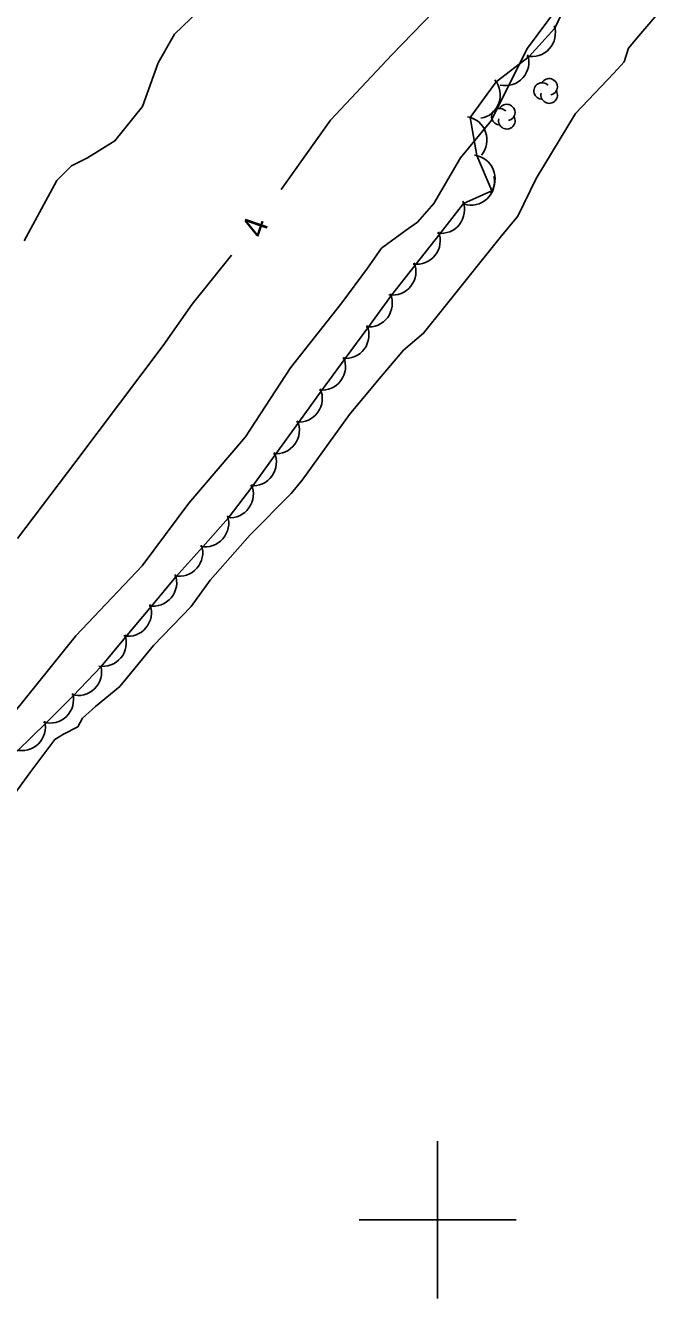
# Model space of a CAD drawing. Extents: x 643342 to 646936, y 5873857 to 5876103.
# Drawn here: x 643747.6 to 643828.6, y 5874190 to 5874351.9 of the extents above; entities that cross this region are included whole.
import ezdxf

# ---------------------------------------------------------------- set-up
doc = ezdxf.new("R2010")
doc.units = 0
for name, color, linetype in [('Niveau 2', 7, 'Continuous'), ('Niveau 4', 7, 'Continuous'), ('Niveau 44', 7, 'Continuous'), ('Niveau 61', 7, 'Continuous')]:
    doc.layers.add(name, color=color, linetype=linetype)

msp = doc.modelspace()

# ---------------------------------------------------------------- linework, layer by layer
at = {"layer": 'Niveau 2'}
for points in [[(643804.54, 5874390.56), (643804.07, 5874388.55), (643802.31, 5874382.88), (643798.29, 5874375.91), (643795.02, 5874372.61), (643787.53, 5874367.58), (643778.06, 5874360.93), (643773.5, 5874357.51), (643769.57, 5874353.78), (643766.51, 5874350.86), (643764.47, 5874347.2), (643762.46, 5874341.64), (643758.95, 5874337.25), (643755.47, 5874335.12), (643753.43, 5874334.09), (643751.58, 5874332.24), (643747.41, 5874324.57)], [(643820.03, 5874382.62), (643819.73, 5874379.12), (643818.86, 5874376.76), (643816.49, 5874374.02), (643810.54, 5874367.46), (643804.84, 5874359.26), (643794.19, 5874348.19), (643786.38, 5874339.91), (643780.1, 5874331.07)], [(643815.37, 5874354.37), (643811.44, 5874349.08), (643806.78, 5874339.78), (643802.91, 5874335.1), (643799.5, 5874329.28), (643797.45, 5874326.93), (643795.89, 5874325.82)], [(643795.89, 5874325.82), (643792.88, 5874323.62), (643791.09, 5874321.06), (643787.8, 5874316.68), (643781.29, 5874308.41), (643775.54, 5874299.62), (643768.34, 5874291.18), (643762.41, 5874283.21), (643753.96, 5874274.29), (643745.96, 5874264.35), (643743.3, 5874261), (643740.19, 5874258.67), (643734.42, 5874254.42), (643726.8, 5874248.33), (643723.45, 5874244.79), (643719.87, 5874239.81), (643715.61, 5874235.83), (643710.48, 5874232.48), (643703.16, 5874228.32), (643692.15, 5874219.41)], [(643773.79, 5874322.73), (643768.77, 5874316.49), (643765.09, 5874311.25), (643753.96, 5874296.47), (643746.54, 5874286.7)]]:
    msp.add_lwpolyline(points, dxfattribs=at)
at = {"layer": 'Niveau 4'}
for points in [[(643822.42, 5874345.87), (643823.73, 5874347.31), (643824.29, 5874349.04), (643825.58, 5874350.61), (643828.61, 5874354.13)], [(643745.89, 5874253.8), (643748.11, 5874256.87), (643751.29, 5874261.11), (643752.41, 5874261.81), (643754.22, 5874262.71), (643754.83, 5874263.84), (643756.48, 5874265.31), (643759.57, 5874267.87), (643763.86, 5874273.06), (643768.63, 5874278.05), (643771.07, 5874281.39), (643776.14, 5874287.13), (643781.36, 5874292.41), (643782.76, 5874294.09), (643788.79, 5874302.44), (643792.33, 5874306.72), (643795.67, 5874310.63), (643798.21, 5874312.79), (643800.78, 5874316.03), (643803.99, 5874320.04), (643807.96, 5874324.97), (643810.21, 5874327.7), (643812.53, 5874332.47), (643817.52, 5874340.73), (643822.42, 5874345.87)]]:
    msp.add_lwpolyline(points, dxfattribs=at)
at = {"layer": 'Niveau 44'}
msp.add_lwpolyline([(643746.52, 5874259.64), (643750.19, 5874263.25), (643753.66, 5874266.65), (643757.2, 5874270.41), (643760.31, 5874274.14), (643763.61, 5874278.09), (643766.72, 5874281.81), (643770.14, 5874285.64), (643773.36, 5874289.28), (643776.5, 5874293.38), (643779.34, 5874297.32), (643782.35, 5874301.49), (643785.18, 5874305.43), (643788.24, 5874309.57), (643791.12, 5874313.48), (643794.12, 5874317.65), (643797.13, 5874321.46), (643800.31, 5874325.5), (643803.31, 5874329.32), (643806.88, 5874330.92), (643804.98, 5874335.39), (643804.12, 5874340.26), (643807.46, 5874344.76), (643811.65, 5874348.01), (643814.91, 5874351.6), (643817.09, 5874356.27)], dxfattribs=at)
for centre, radius, start, end in [((643811.98, 5874350.99), 3, 257.6746, 17.6526), ((643811.98, 5874350.99), 3, 257.6746, 17.6526), ((643811.98, 5874350.99), 3, 257.6746, 17.6526), ((643808.61, 5874347.3), 3, 257.6746, 17.6526), ((643808.61, 5874347.3), 3, 257.6746, 17.6526), ((643808.61, 5874347.3), 3, 257.6746, 17.6526), ((643804.97, 5874343.09), 3, 279.8313, 39.8093), ((643804.97, 5874343.09), 3, 279.8313, 39.8093), ((643804.97, 5874343.09), 3, 279.8313, 39.8093), ((643813.29, 5874343.61), 1.05, 44.1154, 269.804), ((643814.19, 5874344.14), 1.05, 282.2692, 149.7263), ((643814.19, 5874343.09), 1.05, 166.9369, 29.6212), ((643807.9, 5874340.34), 1.05, 44.1154, 269.804), ((643808.8, 5874340.87), 1.05, 282.2692, 149.7263), ((643803.28, 5874337.38), 3, 319.7316, 79.7095), ((643803.28, 5874337.38), 3, 319.7316, 79.7095), ((643803.28, 5874337.38), 3, 319.7316, 79.7095), ((643808.8, 5874339.82), 1.05, 166.9369, 29.6212), ((643804.31, 5874332.46), 3, 323.0145, 82.9924), ((643804.31, 5874332.46), 3, 323.0145, 82.9924), ((643804.31, 5874332.46), 3, 323.0145, 82.9924), ((643804.24, 5874332.08), 3, 252.8421, 12.82), ((643804.24, 5874332.08), 3, 252.8421, 12.82), ((643804.24, 5874332.08), 3, 252.8421, 12.82), ((643800.42, 5874328.5), 3, 261.8085, 21.7864), ((643800.42, 5874328.5), 3, 261.8085, 21.7864), ((643800.42, 5874328.5), 3, 261.8085, 21.7864), ((643797.33, 5874324.57), 3, 261.8085, 21.7864), ((643797.33, 5874324.57), 3, 261.8085, 21.7864), ((643797.33, 5874324.57), 3, 261.8085, 21.7864), ((643794.24, 5874320.64), 3, 261.8085, 21.7864), ((643794.24, 5874320.64), 3, 261.8085, 21.7864), ((643794.24, 5874320.64), 3, 261.8085, 21.7864), ((643791.23, 5874316.59), 3, 263.5747, 23.5526), ((643791.23, 5874316.59), 3, 263.5747, 23.5526), ((643791.23, 5874316.59), 3, 263.5747, 23.5526), ((643788.26, 5874312.57), 3, 263.5747, 23.5526), ((643788.26, 5874312.57), 3, 263.5747, 23.5526), ((643788.26, 5874312.57), 3, 263.5747, 23.5526), ((643785.29, 5874308.55), 3, 263.5747, 23.5526), ((643785.29, 5874308.55), 3, 263.5747, 23.5526), ((643785.29, 5874308.55), 3, 263.5747, 23.5526), ((643782.33, 5874304.49), 3, 264.2496, 24.2276), ((643782.33, 5874304.49), 3, 264.2496, 24.2276), ((643782.33, 5874304.49), 3, 264.2496, 24.2276), ((643779.41, 5874300.44), 3, 264.2496, 24.2276), ((643779.41, 5874300.44), 3, 264.2496, 24.2276), ((643779.41, 5874300.44), 3, 264.2496, 24.2276), ((643776.49, 5874296.38), 3, 264.2496, 24.2276), ((643776.49, 5874296.38), 3, 264.2496, 24.2276), ((643776.49, 5874296.38), 3, 264.2496, 24.2276), ((643773.57, 5874292.32), 3, 264.2496, 24.2276), ((643773.57, 5874292.32), 3, 264.2496, 24.2276), ((643773.57, 5874292.32), 3, 264.2496, 24.2276), ((643770.43, 5874288.63), 3, 258.5726, 18.5506), ((643770.43, 5874288.63), 3, 258.5726, 18.5506), ((643770.43, 5874288.63), 3, 258.5726, 18.5506), ((643767.12, 5874284.88), 3, 258.5726, 18.5506), ((643767.12, 5874284.88), 3, 258.5726, 18.5506), ((643767.12, 5874284.88), 3, 258.5726, 18.5506), ((643763.81, 5874281.08), 3, 260.1488, 20.1268), ((643763.81, 5874281.08), 3, 260.1488, 20.1268), ((643763.81, 5874281.08), 3, 260.1488, 20.1268), ((643760.6, 5874277.24), 3, 260.1488, 20.1268), ((643760.6, 5874277.24), 3, 260.1488, 20.1268), ((643760.6, 5874277.24), 3, 260.1488, 20.1268), ((643757.4, 5874273.41), 3, 260.1488, 20.1268), ((643757.4, 5874273.41), 3, 260.1488, 20.1268), ((643757.4, 5874273.41), 3, 260.1488, 20.1268), ((643754.26, 5874269.71), 3, 254.4607, 14.4386), ((643754.26, 5874269.71), 3, 254.4607, 14.4386), ((643754.26, 5874269.71), 3, 254.4607, 14.4386), ((643750.69, 5874266.2), 3, 254.4607, 14.4386), ((643750.69, 5874266.2), 3, 254.4607, 14.4386), ((643750.69, 5874266.2), 3, 254.4607, 14.4386), ((643747.12, 5874262.7), 3, 254.4607, 14.4386), ((643747.12, 5874262.7), 3, 254.4607, 14.4386), ((643747.12, 5874262.7), 3, 254.4607, 14.4386)]:
    msp.add_arc(centre, radius, start, end, dxfattribs=at)
at = {"layer": 'Niveau 61'}
for points in [[(643800, 5874210), (643800, 5874200), (643800, 5874190)], [(643790, 5874200), (643800, 5874200), (643810, 5874200)]]:
    msp.add_lwpolyline(points, dxfattribs=at)

# ---------------------------------------------------------------- texts
at = {"layer": 'Niveau 2'}
msp.add_text('4', height=3, rotation=71.0689, dxfattribs=at).set_placement((643777.83, 5874324.77))

doc.saveas('drawing.dxf')
